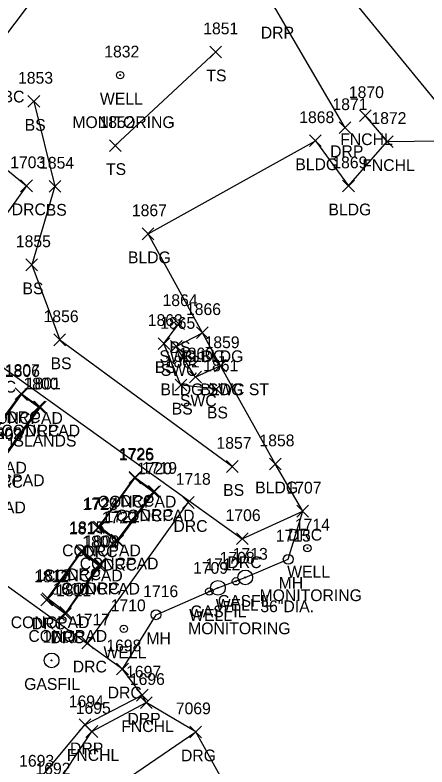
# Model space of a CAD drawing. Extents: x 1769141 to 1770911, y 735471 to 741449.
# Drawn here: x 1770389.6 to 1770459.5, y 736512.6 to 736640.4 of the extents above; entities that cross this region are included whole.
import ezdxf

# ---------------------------------------------------------------- set-up
doc = ezdxf.new("R2010")
doc.units = 0
for name, color, linetype in [('L_A', 7, 'Continuous'), ('L_I', 7, 'Continuous'), ('L_TIC', 7, 'Continuous'), ('LBC', 7, 'Continuous'), ('LELB', 7, 'Continuous'), ('LFNC', 7, 'Continuous'), ('LS', 7, 'Continuous'), ('LSOGP', 7, 'Continuous'), ('PSP', 7, 'Continuous'), ('R_A', 7, 'Continuous'), ('R_C', 7, 'Continuous'), ('R_I', 7, 'Continuous'), ('R_TIC', 7, 'Continuous'), ('RDG', 7, 'Continuous'), ('RDP', 7, 'Continuous'), ('RSW', 7, 'Continuous'), ('U_A', 7, 'Continuous'), ('U_C', 7, 'Continuous'), ('U_I', 7, 'Continuous'), ('UMFC', 7, 'Continuous'), ('UUMH', 7, 'Continuous'), ('UWW', 7, 'Continuous')]:
    doc.layers.add(name, color=color, linetype=linetype)

msp = doc.modelspace()

# ---------------------------------------------------------------- linework, layer by layer
at = {"layer": 'L_TIC'}
for points in [[(1770422.67, 736633.12), (1770424.67, 736635.12)], [(1770424.67, 736633.12), (1770422.67, 736635.12)], [(1770391.77, 736624.72), (1770393.77, 736626.72)], [(1770393.77, 736624.72), (1770391.77, 736626.72)], [(1770448.06, 736622.28), (1770450.06, 736624.28)], [(1770450.06, 736622.28), (1770448.06, 736624.28)], [(1770405.61, 736617.2), (1770407.61, 736619.2)], [(1770407.61, 736617.2), (1770405.61, 736619.2)], [(1770439.59, 736618.02), (1770441.59, 736620.02)], [(1770441.59, 736618.02), (1770439.59, 736620.02)], [(1770451.8, 736617.88), (1770453.8, 736619.88)], [(1770453.8, 736617.88), (1770451.8, 736619.88)], [(1770395.35, 736610.28), (1770397.35, 736612.28)], [(1770397.35, 736610.28), (1770395.35, 736612.28)], [(1770445.22, 736610.34), (1770447.22, 736612.34)], [(1770447.22, 736610.34), (1770445.22, 736612.34)], [(1770411.16, 736602.2), (1770413.16, 736604.2)], [(1770413.16, 736602.2), (1770411.16, 736604.2)], [(1770391.4, 736596.93), (1770393.4, 736598.93)], [(1770393.4, 736596.93), (1770391.4, 736598.93)], [(1770416.37, 736586.92), (1770418.37, 736588.92)], [(1770418.37, 736586.92), (1770416.37, 736588.92)], [(1770420.4, 736585.4), (1770422.4, 736587.4)], [(1770422.4, 736585.4), (1770420.4, 736587.4)], [(1770396.17, 736584.19), (1770398.17, 736586.19)], [(1770398.17, 736584.19), (1770396.17, 736586.19)], [(1770413.86, 736583.54), (1770415.86, 736585.54)], [(1770415.86, 736583.54), (1770413.86, 736585.54)], [(1770423.47, 736579.77), (1770425.47, 736581.77)], [(1770425.47, 736579.77), (1770423.47, 736581.77)], [(1770416.75, 736576.49), (1770418.75, 736578.49)], [(1770418.75, 736576.49), (1770416.75, 736578.49)], [(1770389.68, 736574.89), (1770391.68, 736576.89)], [(1770391.68, 736574.89), (1770389.68, 736576.89)], [(1770422.73, 736575.83), (1770424.73, 736577.83)], [(1770424.73, 736575.83), (1770422.73, 736577.83)], [(1770392.61, 736572.76), (1770394.61, 736574.76)], [(1770394.61, 736572.76), (1770392.61, 736574.76)], [(1770425.49, 736562.66), (1770427.49, 736564.66)], [(1770427.49, 736562.66), (1770425.49, 736564.66)], [(1770432.78, 736563.09), (1770434.78, 736565.09)], [(1770434.78, 736563.09), (1770432.78, 736565.09)], [(1770408.95, 736560.68), (1770410.95, 736562.68)], [(1770410.95, 736560.68), (1770408.95, 736562.68)], [(1770412.06, 736558.32), (1770414.06, 736560.32)], [(1770414.06, 736558.32), (1770412.06, 736560.32)], [(1770402.92, 736552.39), (1770404.92, 736554.39)], [(1770404.92, 736552.39), (1770402.92, 736554.39)], [(1770405.91, 736550.16), (1770407.91, 736552.16)], [(1770407.91, 736550.16), (1770405.91, 736552.16)], [(1770399.85, 736548.11), (1770401.85, 736550.11)], [(1770401.85, 736548.11), (1770399.85, 736550.11)], [(1770402.77, 736545.88), (1770404.77, 736547.88)], [(1770404.77, 736545.88), (1770402.77, 736547.88)], [(1770394.19, 736540.18), (1770396.19, 736542.18)], [(1770396.19, 736540.18), (1770394.19, 736542.18)], [(1770397.19, 736537.85), (1770399.19, 736539.85)], [(1770399.19, 736537.85), (1770397.19, 736539.85)], [(1770410.86, 736522.52), (1770412.86, 736524.52)], [(1770412.86, 736522.52), (1770410.86, 736524.52)], [(1770401.62, 736517.61), (1770403.62, 736519.61)], [(1770403.62, 736517.61), (1770401.62, 736519.61)]]:
    msp.add_lwpolyline(points, dxfattribs=at)
at = {"layer": 'LBC'}
for points in [[(1770466.53, 736619.04), (1770444.69, 736645.78), (1770429.24, 736665.25), (1770437.06, 736676.2), (1770444.96, 736687.56), (1770453.67, 736699.36)], [(1770433.78, 736564.09), (1770424.47, 736580.77), (1770421.4, 736586.4), (1770412.16, 736603.2), (1770440.59, 736619.02), (1770446.22, 736611.34)]]:
    msp.add_lwpolyline(points, dxfattribs=at)
at = {"layer": 'LELB'}
for points in [[(1770423.67, 736634.12), (1770406.61, 736618.2)], [(1770392.77, 736625.72), (1770396.35, 736611.28), (1770392.4, 736597.93), (1770397.17, 736585.19), (1770426.49, 736563.66)], [(1770423.73, 736576.83), (1770417.75, 736577.49), (1770414.86, 736584.54), (1770417.37, 736587.92)]]:
    msp.add_lwpolyline(points, dxfattribs=at)
at = {"layer": 'LFNC'}
for points in [[(1770449.06, 736623.28), (1770452.8, 736618.88)], [(1770354.72, 736502.49), (1770395.78, 736508.31), (1770402.62, 736518.61), (1770411.86, 736523.52)]]:
    msp.add_lwpolyline(points, dxfattribs=at)
at = {"layer": 'LS'}
for points in [[(1770393.61, 736573.76), (1770387.57, 736565.31), (1770384.55, 736567.45), (1770390.68, 736575.89)], [(1770390.68, 736575.89), (1770393.61, 736573.76)], [(1770413.06, 736559.32), (1770406.91, 736551.16), (1770403.92, 736553.39), (1770409.95, 736561.68)], [(1770409.95, 736561.68), (1770413.06, 736559.32)], [(1770403.77, 736546.88), (1770398.19, 736538.85), (1770395.19, 736541.18), (1770400.85, 736549.11)], [(1770400.85, 736549.11), (1770403.77, 736546.88)]]:
    msp.add_lwpolyline(points, dxfattribs=at)
at = {"layer": 'LSOGP'}
msp.add_lwpolyline([(1770428.61, 736503.48), (1770420.27, 736518.54), (1770411.86, 736523.52), (1770411.18, 736524.78), (1770407.82, 736529.23), (1770413.52, 736538.45), (1770424.04, 736543.03), (1770428.68, 736544.81), (1770435.98, 736547.89), (1770438.45, 736556.06), (1770433.78, 736564.09), (1770424.47, 736580.77), (1770421.4, 736586.4), (1770412.16, 736603.2), (1770440.59, 736619.02), (1770446.22, 736611.34), (1770452.8, 736618.88), (1770466.53, 736619.04), (1770490.67, 736653.54)], dxfattribs=at)
at = {"layer": 'PSP'}
msp.add_lwpolyline([(1770340.14, 736567.06), (1770355.71, 736595.48), (1770384.34, 736632.07), (1770413.38, 736670.65), (1770426.21, 736690.9), (1770435.18, 736712.82), (1770460.13, 736745.31), (1770489.93, 736784.13), (1770514.63, 736816.06), (1770535.7, 736843.49), (1770560.97, 736877.11), (1770581.17, 736903.18), (1770605.6, 736937.84), (1770621.17, 736966.95), (1770635.97, 737003.98), (1770646.02, 737037.66), (1770650.84, 737066.81), (1770652.59, 737098.8), (1770650.92, 737139.65), (1770647.51, 737164.15), (1770640.68, 737197.77), (1770629.07, 737231.11), (1770614.09, 737275.47)], dxfattribs=at)
at = {"layer": 'R_TIC'}
for points in [[(1770444.62, 736620.23), (1770446.62, 736622.23)], [(1770446.62, 736620.23), (1770444.62, 736622.23)], [(1770390.52, 736610.36), (1770392.52, 736612.36)], [(1770392.52, 736610.36), (1770390.52, 736612.36)], [(1770420.4, 736585.4), (1770422.4, 736587.4)], [(1770422.4, 736585.4), (1770420.4, 736587.4)], [(1770415.97, 736583.06), (1770417.97, 736585.06)], [(1770417.97, 736583.06), (1770415.97, 736585.06)], [(1770423.47, 736579.77), (1770425.47, 736581.77)], [(1770425.47, 736579.77), (1770423.47, 736581.77)], [(1770419.23, 736577.86), (1770421.23, 736579.86)], [(1770421.23, 736577.86), (1770419.23, 736579.86)], [(1770389.61, 736575.04), (1770391.61, 736577.04)], [(1770391.61, 736575.04), (1770389.61, 736577.04)], [(1770392.84, 736572.75), (1770394.84, 736574.75)], [(1770394.84, 736572.75), (1770392.84, 736574.75)], [(1770408.94, 736560.82), (1770410.94, 736562.82)], [(1770410.94, 736560.82), (1770408.94, 736562.82)], [(1770412.26, 736558.41), (1770414.26, 736560.41)], [(1770414.26, 736558.41), (1770412.26, 736560.41)], [(1770418, 736556.54), (1770420, 736558.54)], [(1770420, 736556.54), (1770418, 736558.54)], [(1770437.45, 736555.06), (1770439.45, 736557.06)], [(1770439.45, 736555.06), (1770437.45, 736557.06)], [(1770402.7, 736552.24), (1770404.7, 736554.24)], [(1770404.7, 736552.24), (1770402.7, 736554.24)], [(1770406.01, 736549.97), (1770408.01, 736551.97)], [(1770408.01, 736549.97), (1770406.01, 736551.97)], [(1770427.17, 736550.38), (1770429.17, 736552.38)], [(1770429.17, 736550.38), (1770427.17, 736552.38)], [(1770399.93, 736548.33), (1770401.93, 736550.33)], [(1770401.93, 736548.33), (1770399.93, 736550.33)], [(1770403.1, 736545.94), (1770405.1, 736547.94)], [(1770405.1, 736545.94), (1770403.1, 736547.94)], [(1770393.93, 736539.97), (1770395.93, 736541.97)], [(1770395.93, 736539.97), (1770393.93, 736541.97)], [(1770397.1, 736537.6), (1770399.1, 736539.6)], [(1770399.1, 736537.6), (1770397.1, 736539.6)], [(1770400.9, 736532.64), (1770402.9, 736534.64)], [(1770402.9, 736532.64), (1770400.9, 736534.64)], [(1770406.82, 736528.23), (1770408.82, 736530.23)], [(1770408.82, 736528.23), (1770406.82, 736530.23)], [(1770410.18, 736523.78), (1770412.18, 736525.78)], [(1770412.18, 736523.78), (1770410.18, 736525.78)], [(1770400.44, 736518.74), (1770402.44, 736520.74)], [(1770402.44, 736518.74), (1770400.44, 736520.74)], [(1770419.27, 736517.54), (1770421.27, 736519.54)], [(1770421.27, 736517.54), (1770419.27, 736519.54)]]:
    msp.add_lwpolyline(points, dxfattribs=at)
at = {"layer": 'RDG'}
msp.add_lwpolyline([(1770350.83, 736500.43), (1770352.46, 736496.8), (1770366.48, 736494.7), (1770386.69, 736498.64), (1770400.05, 736504.73), (1770420.27, 736518.54)], dxfattribs=at)
at = {"layer": 'RDP'}
for points in [[(1770413.38, 736670.65), (1770416.24, 736654.93), (1770422.77, 736657.52), (1770433.83, 736641.4), (1770445.62, 736621.23)], [(1770407.82, 736529.23), (1770369.39, 736556.84), (1770354.21, 736581.5), (1770365.72, 736596.38), (1770382.74, 736618.54), (1770391.52, 736611.36), (1770384.16, 736601.09), (1770386.47, 736581.21), (1770428.17, 736551.38), (1770438.45, 736556.06)], [(1770393.84, 736573.75), (1770387.63, 736565.04), (1770384.25, 736567.45), (1770390.61, 736576.04)], [(1770390.61, 736576.04), (1770393.84, 736573.75)], [(1770413.26, 736559.41), (1770407.01, 736550.97), (1770403.7, 736553.24), (1770409.94, 736561.82)], [(1770409.94, 736561.82), (1770413.26, 736559.41)], [(1770401.9, 736533.64), (1770419, 736557.54)], [(1770404.1, 736546.94), (1770398.1, 736538.6), (1770394.93, 736540.97), (1770400.93, 736549.33)], [(1770400.93, 736549.33), (1770404.1, 736546.94)], [(1770350.59, 736502.97), (1770353.52, 736505.17), (1770393.01, 736509.63), (1770401.44, 736519.74), (1770411.18, 736524.78)]]:
    msp.add_lwpolyline(points, dxfattribs=at)
at = {"layer": 'RSW'}
msp.add_lwpolyline([(1770424.47, 736580.77), (1770420.23, 736578.86), (1770416.97, 736584.06), (1770421.4, 736586.4)], dxfattribs=at)
at = {"layer": 'UMFC'}
for p, q in [((1770428.68, 736544.81), (1770428.68, 736544.81)), ((1770424.04, 736543.03), (1770424.04, 736543.03)), ((1770395.79, 736530.69), (1770395.79, 736530.69))]:
    msp.add_line(p, q, dxfattribs=at)
for centre, radius in [((1770428.68, 736544.81), 1.25), ((1770428.68, 736544.81), 0.0833), ((1770424.04, 736543.03), 1.25), ((1770424.04, 736543.03), 0.0833), ((1770395.79, 736530.69), 1.25), ((1770395.79, 736530.69), 0.0833)]:
    msp.add_circle(centre, radius, dxfattribs=at)
at = {"layer": 'UUMH'}
for p, q in [((1770435.98, 736547.89), (1770435.98, 736547.89)), ((1770436.82, 736547.89), (1770436.82, 736547.89)), ((1770413.52, 736538.45), (1770413.52, 736538.45)), ((1770414.35, 736538.45), (1770414.35, 736538.45))]:
    msp.add_line(p, q, dxfattribs=at)
for centre in [(1770435.98, 736547.89), (1770413.52, 736538.45)]:
    msp.add_circle(centre, 0.833, dxfattribs=at)
at = {"layer": 'UWW'}
for centre, radius in [((1770407.42, 736630.18), 0.625), ((1770407.42, 736630.18), 0.0833), ((1770439.23, 736549.77), 0.625), ((1770439.23, 736549.77), 0.0833), ((1770427.1, 736544.14), 0.625), ((1770427.1, 736544.14), 0.0833), ((1770422.58, 736542.42), 0.625), ((1770422.58, 736542.42), 0.0833), ((1770408.04, 736536.06), 0.625), ((1770408.04, 736536.06), 0.0833)]:
    msp.add_circle(centre, radius, dxfattribs=at)

# ---------------------------------------------------------------- texts
at = {"layer": 'L_A'}
for s, p in [('TS', (1770422.08, 736629.12)), ('BS', (1770391.21, 736620.72)), ('FNCHL', (1770444.81, 736618.28)), ('TS', (1770405.02, 736613.2)), ('BLDG', (1770437.18, 736614.02)), ('FNCHL', (1770448.55, 736613.88)), ('BS', (1770394.79, 736606.28)), ('BLDG', (1770442.81, 736606.34)), ('BLDG', (1770408.75, 736598.2)), ('BS', (1770390.84, 736592.93)), ('BS', (1770415.81, 736582.92)), ('BLDG', (1770417.99, 736581.4)), ('BS', (1770395.61, 736580.19)), ('BS', (1770413.31, 736579.54)), ('BLDG', (1770421.06, 736575.77)), ('BS', (1770416.19, 736572.49)), ('CONCPAD', (1770384.32, 736570.89)), ('BS', (1770422.17, 736571.83)), ('CONCPAD', (1770387.25, 736568.76)), ('CONCPAD', (1770378.2, 736562.45)), ('CONCPAD', (1770381.22, 736560.31)), ('BS', (1770424.93, 736558.66)), ('BLDG', (1770430.37, 736559.09)), ('CONCPAD', (1770378.03, 736555.7)), ('CONCPAD', (1770403.6, 736556.68)), ('CONCPAD', (1770406.7, 736554.32)), ('CONCPAD', (1770397.57, 736548.39)), ('CONCPAD', (1770400.56, 736546.16)), ('CONCPAD', (1770394.49, 736544.11)), ('CONCPAD', (1770397.42, 736541.88)), ('CONCPAD', (1770388.84, 736536.18)), ('CONCPAD', (1770391.84, 736533.85)), ('FNCHL', (1770407.61, 736518.52)), ('FNCHL', (1770398.36, 736513.61))]:
    msp.add_text(s, height=2, dxfattribs=at).set_placement(p)
at = {"layer": 'L_I'}
for s, p in [('1851', (1770421.54, 736637.12)), ('1853', (1770390.08, 736628.72)), ('1870', (1770446.28, 736626.28)), ('1868', (1770437.85, 736622.02)), ('1852', (1770403.92, 736621.2)), ('1872', (1770450.11, 736621.88)), ('1854', (1770393.66, 736614.28)), ('1869', (1770443.47, 736614.34)), ('1867', (1770409.42, 736606.2)), ('1855', (1770389.71, 736600.93)), ('1864', (1770414.63, 736590.92)), ('1866', (1770418.61, 736589.4)), ('1856', (1770394.42, 736588.19)), ('1863', (1770412.12, 736587.54)), ('1859', (1770421.77, 736583.77)), ('1862', (1770415.01, 736580.49)), ('1861', (1770421.55, 736579.83)), ('1806', (1770387.85, 736578.89)), ('1801', (1770391.4, 736576.76)), ('1802', (1770384.8, 736568.31)), ('1858', (1770431.09, 736567.09)), ('1857', (1770423.79, 736566.66)), ('1725', (1770407.26, 736564.68)), ('1720', (1770410.28, 736562.32)), ('1724', (1770401.23, 736556.39)), ('1721', (1770404.79, 736554.16)), ('1814', (1770398.72, 736552.11)), ('1809', (1770401, 736549.88)), ('1813', (1770393.07, 736544.18)), ('1810', (1770395.98, 736541.85)), ('1696', (1770409.07, 736526.52)), ('1695', (1770399.88, 736521.61)), ('1692', (1770393.04, 736511.31))]:
    msp.add_text(s, height=2, dxfattribs=at).set_placement(p)
at = {"layer": 'R_A'}
for s, p in [('DRP', (1770431.32, 736636.4)), ('CURBC', (1770381.66, 736625.53)), ('DRP', (1770443.1, 736616.23)), ('DRC', (1770389.01, 736606.36)), ('SWC BLDG', (1770414.09, 736581.4)), ('SWC', (1770414.33, 736579.06)), ('DRC', (1770383.96, 736576.21)), ('BLDG SWC ST', (1770414.28, 736575.77)), ('SWC', (1770417.59, 736573.86)), ('DRC', (1770388.1, 736571.04)), ('DRC', (1770391.33, 736568.75)), ('DRC', (1770385.12, 736560.04)), ('DRC', (1770407.43, 736556.82)), ('DRC', (1770410.75, 736554.41)), ('DRC', (1770416.48, 736552.54)), ('DRC', (1770435.94, 736551.06)), ('DRC', (1770401.19, 736548.24)), ('DRC', (1770404.5, 736545.97)), ('DRC', (1770425.66, 736546.38)), ('DRC', (1770398.42, 736544.33)), ('DRC', (1770401.59, 736541.94)), ('DRC', (1770392.42, 736535.97)), ('DRC', (1770395.59, 736533.6)), ('DRC', (1770399.38, 736528.64)), ('DRC', (1770405.31, 736524.23)), ('DRP', (1770408.67, 736519.78)), ('DRP', (1770398.92, 736514.74)), ('DRG', (1770417.76, 736513.54))]:
    msp.add_text(s, height=2, dxfattribs=at).set_placement(p)
at = {"layer": 'R_C'}
msp.add_text('PUMP ISLANDS', height=2, dxfattribs=at).set_placement((1770380.09, 736567.04))
at = {"layer": 'R_I'}
for s, p in [('1871', (1770443.49, 736624.23)), ('1703', (1770388.75, 736614.36)), ('1866', (1770418.61, 736589.4)), ('1865', (1770414.23, 736587.06)), ('1859', (1770421.77, 736583.77)), ('1860', (1770417.4, 736581.86)), ('1807', (1770387.84, 736579.04)), ('1800', (1770390.99, 736576.75)), ('1803', (1770384.86, 736568.04)), ('1726', (1770407.19, 736564.82)), ('1719', (1770411.13, 736562.41)), ('1718', (1770416.87, 736560.54)), ('1707', (1770435.68, 736559.06)), ('1723', (1770401.01, 736556.24)), ('1706', (1770425.34, 736554.38)), ('1722', (1770404.31, 736553.97)), ('1815', (1770398.8, 736552.33)), ('1808', (1770401.33, 736549.94)), ('1812', (1770392.8, 736543.97)), ('1811', (1770396.54, 736541.6)), ('1717', (1770399.77, 736536.64)), ('1698', (1770405.08, 736532.23)), ('1697', (1770408.44, 736527.78)), ('1694', (1770398.7, 736522.74)), ('7069', (1770416.88, 736521.54)), ('1693', (1770390.27, 736512.63))]:
    msp.add_text(s, height=2, dxfattribs=at).set_placement(p)
at = {"layer": 'U_A'}
for s, p in [('WELL', (1770403.99, 736625.18)), ('WELL', (1770435.8, 736544.77)), ('MH', (1770434.35, 736542.89)), ('WELL', (1770423.67, 736539.14)), ('GASFIL', (1770424.02, 736539.81)), ('GASFIL', (1770419.37, 736538.03)), ('WELL', (1770419.15, 736537.42)), ('MH', (1770411.88, 736533.45)), ('WELL', (1770404.6, 736531.06)), ('GASFIL', (1770391.12, 736525.69))]:
    msp.add_text(s, height=2, dxfattribs=at).set_placement(p)
at = {"layer": 'U_C'}
for s, p in [('MONITORING', (1770399.31, 736621.18)), ('MONITORING', (1770431.11, 736540.77)), ('36"DIA.', (1770431.24, 736538.89)), ('MONITORING', (1770418.98, 736535.14))]:
    msp.add_text(s, height=2, dxfattribs=at).set_placement(p)
at = {"layer": 'U_I'}
for s, p in [('1832', (1770404.73, 736633.18)), ('1714', (1770437.11, 736552.77)), ('1715', (1770433.86, 736550.89)), ('1713', (1770426.56, 736547.81)), ('1708', (1770424.33, 736547.14)), ('1709', (1770419.81, 736545.42)), ('1712', (1770421.91, 736546.03)), ('1716', (1770411.34, 736541.45)), ('1710', (1770405.82, 736539.06)), ('1711', (1770394.23, 736533.69))]:
    msp.add_text(s, height=2, dxfattribs=at).set_placement(p)

doc.saveas('drawing.dxf')
